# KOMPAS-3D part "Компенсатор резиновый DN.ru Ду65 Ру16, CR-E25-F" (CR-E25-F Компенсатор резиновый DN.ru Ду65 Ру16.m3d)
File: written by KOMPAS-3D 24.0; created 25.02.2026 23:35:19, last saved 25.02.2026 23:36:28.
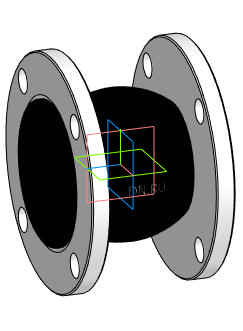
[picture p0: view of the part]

Document properties: Автор: DN.RU; Полное имя файла: D:\PROJECT CAD\DN.RU\...178(4)(ACTUALE). CR-E25-F Компенсатор резиновый DN.ru Ру10-16\DN65_PN16\CR-E25-F Компенсатор резиновый DN.ru Ду65 Ру16.m3d

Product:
- Body: Твердое тело2  | qty 1
    Масса: 7.29646
- Part/product: Компенсатор резиновый DN.ru Ду65 Ру16  | designation CR-E25-F
    Масса: 5.88
    Раздел спецификации: Прочие изделия
    Комментарий: D140-02174
    Примечание: D140-02174
    additional columns: Типовые

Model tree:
1. Твердое тело2  (labels: Твердое тело2)

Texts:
  CR-E25-F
